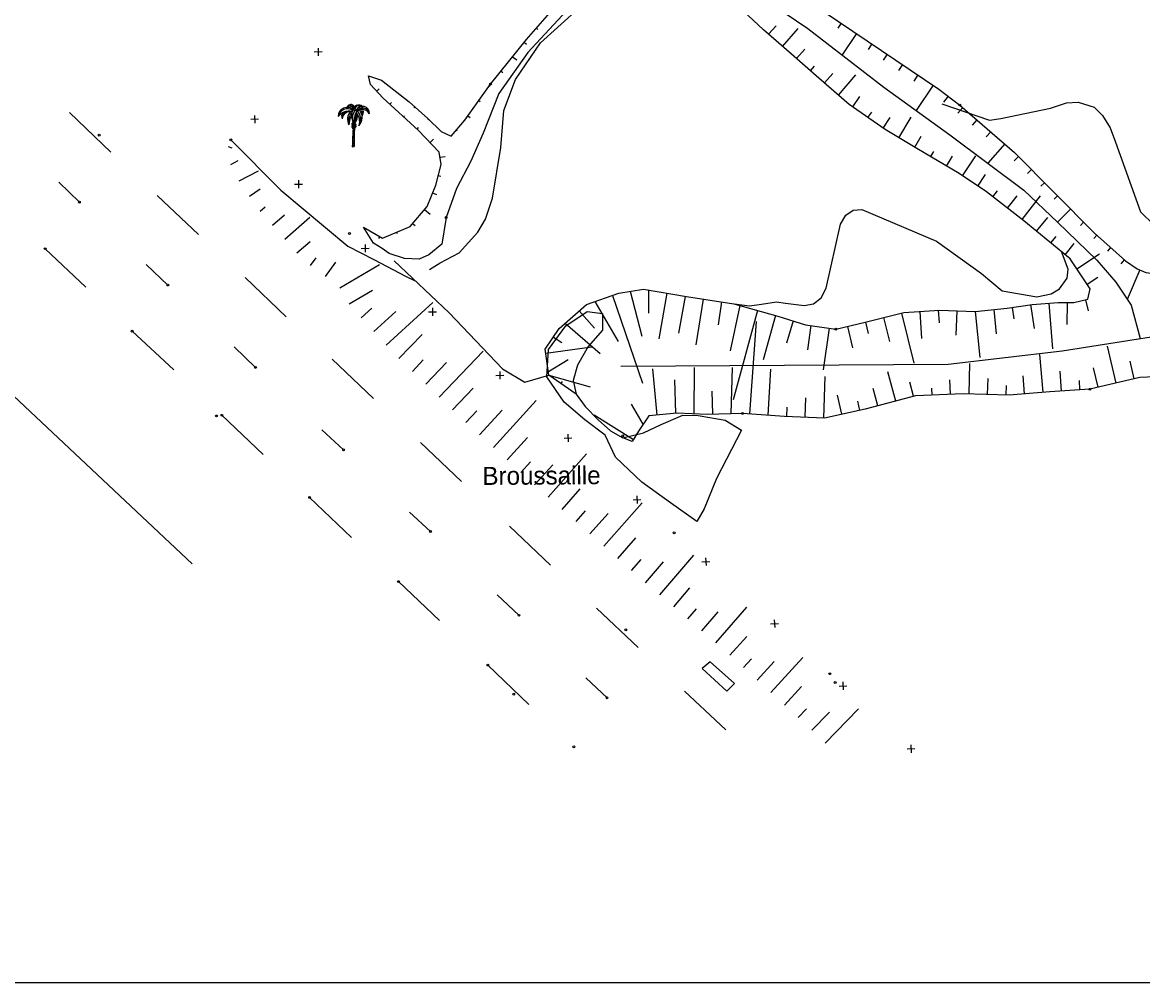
# Model space of a CAD drawing. Extents: x 344013 to 344423, y 298505 to 298795.
# Drawn here: x 344122.6 to 344183.1, y 298504.9 to 298556.7 of the extents above; entities that cross this region are included whole.
import ezdxf

# ---------------------------------------------------------------- set-up
doc = ezdxf.new("R2010")
doc.units = 0
for name, color, linetype in [('Default', 7, 'Continuous'), ('DH_CADRE -CARTOUCHE', 7, 'Continuous'), ('IMM_DIVERS', 7, 'Continuous'), ('IMM_VOIRIE VOIE FERREE', 7, 'Continuous'), ('PC_CONCRETE', 7, 'Continuous'), ('PS_CONST', 7, 'Continuous'), ('PS_DAWA', 7, 'Continuous'), ('PS_KOTE', 7, 'Continuous'), ('PS_WELD', 7, 'Continuous'), ('TOPO_COURBE NIVEAU', 7, 'Continuous'), ('TOPO_POINT', 7, 'Continuous'), ('TOPO_TALUS-TERRAIN NATUREL', 7, 'Continuous'), ('VOIRIE_ESPACE VERT', 7, 'Continuous')]:
    doc.layers.add(name, color=color, linetype=linetype)

# ---------------------------------------------------------------- blocks, each defined once
blk = doc.blocks.new('POINT_DISPLAY')
at = {"layer": 'Default'}
blk.add_circle((0, 0), 0.05, dxfattribs=at)
blk = doc.blocks.new('PALMIER')
at = {"layer": 'Default'}
for p, q in [((-0.036, 0.77), (0.064, 0.807)), ((0.066, 0.879), (-0.031, 0.865)), ((-0.027, 0.942), (0.068, 0.953)), ((0.07, 1.023), (-0.02, 1.046)), ((-0.016, 1.111), (0.072, 1.097)), ((-0.062, 0.035), (0.058, 0.076)), ((0.058, 0.159), (-0.059, 0.156)), ((-0.057, 0.24), (0.058, 0.243)), ((0.058, 0.341), (-0.054, 0.323)), ((-0.051, 0.409), (0.059, 0.425)), ((0.06, 0.53), (-0.047, 0.516))]:
    blk.add_line(p, q, dxfattribs=at)
blk.add_lwpolyline([(-0.044, 0.591), (0.061, 0.593), (0.062, 0.664), (-0.041, 0.672)], dxfattribs=at)
for centre, radius, start, end in [((-0.427, 2.014), 0.606, 43.75383, 181.60417), ((-0.287, 1.433), 0.935, 76.88066, 142.94423), ((-0.379, 1.861), 0.66, 58.06089, 166.76184), ((-0.191, 1.77), 0.575, 78.65572, 171.49215), ((-0.318, 1.955), 0.441, 119.22507, 188.90379), ((-0.119, 2.5), 0.329, 122.48917, 158.90528), ((-0.196, 2.528), 0.242, 4.66355, 154.2427), ((-0.249, 2.465), 0.236, 4.38583, 134.35204), ((0.377, 1.821), 0.768, 136.85301, 208.9638), ((0.57, 1.687), 0.895, 137.87473, 194.5133), ((-0.156, 2.558), 0.26, 21.2278, 122.48917), ((0.64, 2.063), 0.767, 153.22849, 230.25415), ((0.679, 1.97), 0.731, 142.49709, 222.42113), ((0, 2.373), 0.0573, 81.88924, 144.44525), ((-0.182, 1.095), 1.349, 71.51318, 81.88924), ((0.39, 2.418), 0.379, 113.90981, 175.47265), ((0.39, 2.418), 0.379, 113.90981, 175.47265), ((0.306, 2.506), 0.261, 198.81826, 199.90438), ((0.989, 1.84), 0.917, 144.12827, 203.57056), ((0.433, 2.437), 0.332, 97.26656, 184.09287), ((1.052, 1.956), 0.976, 126.82753, 153.3081), ((0.609, 1.916), 0.559, 29.70715, 139.49343), ((-0.544, 1.637), 0.978, 345.01981, 41.28777), ((-0.338, 1.796), 0.844, 47.11841, 50.26484), ((0.636, 2.223), 0.459, 356.30437, 159.14261), ((0.629, 2.092), 0.477, 12.24944, 148.4563), ((0.357, 2.315), 0.459, 69.22345, 105.00376), ((-0.152, 1.926), 0.754, 51.38923, 54.66342), ((-0.338, 1.796), 0.844, 334.21038, 41.33572), ((-1.014, 1.466), 1.819, 37.7085, 40.65735), ((-0.152, 1.926), 0.754, 315.28888, 39.16564), ((-0.251, 2.185), 0.885, 28.61423, 37.23825), ((0.508, 2.682), 0.0691, 35.46223, 126.82753), ((-1.727, 1.741), 2.37, 7.73955, 16.5083), ((-0.048, 2.285), 0.752, 25.96116, 35.46223), ((-0.251, 2.185), 0.885, 351.03001, 14.84805), ((-0.484, 2.461), 1.182, 339.50138, 356.73425), ((-0.298, 2.021), 0.491, 151.27485, 199.73594), ((0.671, 1.493), 0.966, 145.65628, 182.59451), ((-0.285, 1.344), 0.284, 348.96741, 47.50384), ((24.236, -0.46), 24.303, 175.11756, 178.94339), ((-0.275, 1.529), 0.286, 2.29159, 36.77418), ((-0.586, 1.323), 0.604, 357.22259, 24.49773), ((-0.26, 1.395), 0.322, 340.14145, 25.86455), ((0.212, 1.553), 0.18, 167.08602, 185.73834), ((27.948, 0.208), 27.89, 177.28613, 180.41366), ((0.563, 1.714), 0.483, 137.33705, 173.04039), ((0.322, 1.915), 0.23, 121.57139, 182.43168), ((27.823, 0.039), 27.774, 175.62083, 176.70143), ((0.325, 2.055), 0.223, 141.99767, 191.65918), ((0.388, 1.745), 0.282, 133.73732, 173.62872), ((0.832, 1.435), 0.791, 142.37749, 156.42174), ((0.255, 1.864), 0.149, 111.11446, 166.11729), ((0.42, 1.776), 0.361, 125.20026, 146.53098), ((0.414, 2.001), 0.306, 136.59859, 162.21026), ((0.372, 1.986), 0.249, 133.26007, 172.89513), ((-0.764, 1.855), 0.939, 344.99226, 16.04048), ((-0.403, 1.944), 0.63, 329.60827, 26.82103), ((-0.287, 2.01), 0.575, 317.96962, 12.48027), ((-0.205, 1.197), 0.169, 353.50598, 55.12107), ((-0.721, 1.091), 0.712, 9.15549, 26.66867), ((-0.349, 1.239), 0.371, 353.62318, 41.34943), ((0.287, 1.204), 0.266, 120.40763, 191.54922), ((0.343, 1.162), 0.295, 120.97799, 179.22943), ((0.244, 1.306), 0.167, 110.73571, 185.35669), ((0.507, 1.019), 0.45, 131.01759, 160.16859)]:
    blk.add_arc(centre, radius, start, end, dxfattribs=at)

msp = doc.modelspace()

# ---------------------------------------------------------------- linework, layer by layer
at = {"layer": 'DH_CADRE -CARTOUCHE'}
msp.add_lwpolyline([(344012.906, 298504.876), (344422.906, 298504.876), (344422.906, 298791.876), (344012.906, 298791.876)], close=True, dxfattribs=at)
at = {"layer": 'IMM_DIVERS'}
for centre in [(344151.975, 298528.79), (344140.897, 298525.565)]:
    msp.add_arc(centre, 1, 0, 0, dxfattribs=at)
at = {"layer": 'IMM_VOIRIE VOIE FERREE'}
for points in [[(344127.346, 298549.738), (344125.107, 298551.875)], [(344125.639, 298547.029), (344124.523, 298548.117)], [(344132.077, 298545.276), (344129.837, 298547.397)], [(344123.791, 298544.517), (344125.99, 298542.437)], [(344130.414, 298542.553), (344129.244, 298543.664)], [(344136.806, 298540.831), (344134.598, 298542.952)], [(344128.495, 298540.066), (344130.735, 298537.978)], [(344135.16, 298538.107), (344133.997, 298539.21)], [(344141.52, 298536.432), (344139.289, 298538.545)], [(344133.343, 298535.519), (344135.566, 298533.399)], [(344139.914, 298533.653), (344138.735, 298534.741)], [(344146.274, 298531.947), (344144.059, 298534.043)], [(344138.078, 298531.083), (344140.341, 298528.924)], [(344144.612, 298529.238), (344143.481, 298530.279)], [(344151.096, 298527.424), (344148.882, 298529.52)], [(344142.879, 298526.535), (344145.095, 298524.438)], [(344149.388, 298524.714), (344148.21, 298525.818)], [(344155.833, 298522.971), (344153.578, 298525.107)], [(344147.702, 298522.027), (344149.917, 298519.898)], [(344154.142, 298520.26), (344153.002, 298521.342)], [(344160.554, 298518.534), (344158.323, 298520.614)]]:
    msp.add_lwpolyline(points, dxfattribs=at)
at = {"layer": 'PC_CONCRETE'}
msp.add_lwpolyline([(344142.636, 298543.855), (344145.621, 298541.05), (344148.504, 298538.031), (344149.7, 298537.305), (344151.002, 298537.69), (344153.228, 298537.051)], dxfattribs=at)
at = {"layer": 'PS_DAWA'}
msp.add_lwpolyline([(344017.676, 298634.726), (344131.741, 298527.493)], dxfattribs=at)
at = {"layer": 'PS_KOTE'}
msp.add_lwpolyline([(344159.287, 298521.843), (344160.623, 298520.612), (344161.025, 298521.029), (344159.721, 298522.195), (344159.287, 298521.843)], dxfattribs=at)
at = {"layer": 'PS_WELD'}
for p, q in [((344138.754, 298555.144), (344138.33, 298555.132)), ((344138.536, 298555.35), (344138.548, 298554.926)), ((344135.318, 298551.511), (344134.894, 298551.499)), ((344135.1, 298551.717), (344135.112, 298551.293)), ((344137.474, 298548.214), (344137.481, 298547.79)), ((344137.265, 298547.998), (344137.69, 298548.005)), ((344140.869, 298544.53), (344141.293, 298544.542)), ((344141.075, 298544.748), (344141.087, 298544.324)), ((344144.506, 298541.098), (344144.93, 298541.111)), ((344144.712, 298541.317), (344144.724, 298540.893)), ((344148.349, 298537.885), (344148.361, 298537.461)), ((344148.143, 298537.667), (344148.567, 298537.679)), ((344151.823, 298534.277), (344152.247, 298534.301)), ((344152.023, 298534.501), (344152.047, 298534.077)), ((344155.55, 298530.945), (344155.974, 298530.968)), ((344155.75, 298531.168), (344155.774, 298530.745)), ((344159.269, 298527.604), (344159.693, 298527.625)), ((344159.47, 298527.826), (344159.492, 298527.402)), ((344162.978, 298524.25), (344163.402, 298524.272)), ((344163.179, 298524.473), (344163.201, 298524.049)), ((344166.68, 298520.892), (344167.104, 298520.908)), ((344166.883, 298521.112), (344166.9, 298520.688)), ((344170.351, 298517.498), (344170.775, 298517.514)), ((344170.555, 298517.718), (344170.572, 298517.294))]:
    msp.add_line(p, q, dxfattribs=at)
at = {"layer": 'TOPO_COURBE NIVEAU'}
for points in [[(344144.559, 298543.398), (344145.126, 298543.758), (344146.164, 298544.291), (344147.173, 298545.407), (344147.575, 298546.106), (344147.955, 298547.238), (344148.408, 298549.983), (344148.576, 298551.974), (344149.201, 298553.647), (344150.556, 298555.627), (344153.701, 298558.494), (344155.669, 298559.733), (344159.453, 298560.805), (344165.265, 298563.828)], [(344172.229, 298552.34), (344174.81, 298551.459), (344175.417, 298551.545), (344178.101, 298552.1), (344178.967, 298552.397), (344179.598, 298552.428), (344180.464, 298552.159), (344180.902, 298551.719), (344181.319, 298551.048), (344181.616, 298550.278), (344182.963, 298546.5), (344184.44, 298545.064), (344185.14, 298544.773), (344186.698, 298544.755), (344187.508, 298545.028), (344188.162, 298545.491), (344188.533, 298546.018), (344189.189, 298547.821), (344189.573, 298551.818), (344189.112, 298553.182), (344189.034, 298554.487), (344189.312, 298556.099), (344189.48, 298557.412)], [(344161.011, 298541.531), (344161.835, 298541.435), (344162.489, 298541.521), (344163.292, 298541.645), (344163.787, 298541.574), (344164.801, 298541.439), (344165.305, 298541.532), (344165.715, 298541.862), (344165.983, 298542.381), (344166.752, 298545.848), (344167.036, 298546.319), (344167.438, 298546.595), (344167.902, 298546.633), (344171.944, 298544.926), (344174.372, 298543.184), (344175.479, 298542.247), (344177.36, 298541.921), (344178.139, 298542.085), (344178.58, 298542.352), (344179.006, 298542.933), (344179.054, 298543.405), (344178.687, 298544.359)]]:
    msp.add_lwpolyline(points, dxfattribs=at)
at = {"layer": 'TOPO_TALUS-TERRAIN NATUREL'}
for p, q in [((344166.793, 298556.702), (344166.605, 298556.424)), ((344150.325, 298556.424), (344150.398, 298556.361)), ((344162.871, 298556.096), (344163.272, 298556.558)), ((344163.626, 298555.44), (344164.472, 298556.414)), ((344167.621, 298556.142), (344166.836, 298554.98)), ((344149.674, 298555.665), (344149.802, 298555.562)), ((344168.45, 298555.582), (344168.244, 298555.278)), ((344149.045, 298554.887), (344149.265, 298554.71)), ((344164.38, 298554.783), (344164.828, 298555.295)), ((344169.278, 298555.022), (344169.064, 298554.705)), ((344165.133, 298554.125), (344165.346, 298554.368)), ((344170.107, 298554.462), (344169.884, 298554.133)), ((344141.287, 298553.836), (344141.279, 298553.812)), ((344148.417, 298554.109), (344148.511, 298554.033)), ((344165.887, 298553.467), (344166.334, 298553.982)), ((344166.642, 298552.812), (344167.586, 298553.898)), ((344170.935, 298553.902), (344170.708, 298553.566)), ((344141.705, 298553.025), (344141.842, 298553.153)), ((344142.19, 298553.436), (344142.181, 298553.424)), ((344147.794, 298553.327), (344147.835, 298553.297)), ((344171.764, 298553.342), (344170.839, 298551.974)), ((344142.415, 298552.322), (344142.497, 298552.412)), ((344142.982, 298552.824), (344142.961, 298552.797)), ((344147.213, 298552.512), (344147.285, 298552.461)), ((344167.413, 298552.175), (344167.803, 298552.736)), ((344172.572, 298552.754), (344172.324, 298552.426)), ((344143.753, 298552.188), (344143.699, 298552.129)), ((344168.234, 298551.604), (344168.44, 298551.899)), ((344173.361, 298552.14), (344173.096, 298551.835)), ((344143.154, 298551.648), (344143.197, 298551.695)), ((344144.492, 298551.514), (344144.459, 298551.481)), ((344146.633, 298551.697), (344146.756, 298551.61)), ((344169.055, 298551.032), (344169.446, 298551.594)), ((344169.908, 298550.511), (344170.575, 298551.627)), ((344174.115, 298551.483), (344173.863, 298551.194)), ((344143.892, 298550.973), (344143.966, 298551.054)), ((344145.213, 298550.824), (344145.202, 298550.799)), ((344146.008, 298550.917), (344146.057, 298550.876)), ((344170.767, 298549.998), (344171.119, 298550.587)), ((344174.87, 298550.827), (344174.63, 298550.552)), ((344133.686, 298550.042), (344133.885, 298549.964)), ((344144.584, 298550.251), (344144.772, 298550.428)), ((344175.624, 298550.171), (344174.716, 298549.127)), ((344145.122, 298549.451), (344145.404, 298549.494)), ((344171.626, 298549.487), (344171.793, 298549.767)), ((344172.486, 298548.975), (344172.802, 298549.507)), ((344173.339, 298548.454), (344174.068, 298549.537)), ((344176.364, 298549.498), (344176.133, 298549.27)), ((344133.816, 298549.071), (344134.218, 298549.276)), ((344177.068, 298548.788), (344176.864, 298548.586)), ((344134.271, 298548.18), (344135.318, 298548.716)), ((344145.028, 298548.475), (344145.159, 298548.441)), ((344174.169, 298547.895), (344174.596, 298548.53)), ((344134.835, 298547.354), (344135.402, 298547.747)), ((344144.722, 298547.525), (344144.936, 298547.438)), ((344174.983, 298547.315), (344175.229, 298547.634)), ((344177.772, 298548.078), (344177.584, 298547.892)), ((344175.776, 298546.704), (344176.296, 298547.38)), ((344176.568, 298546.094), (344177.556, 298547.377)), ((344178.476, 298547.368), (344178.294, 298547.187)), ((344135.411, 298546.537), (344135.685, 298546.778)), ((344136.072, 298545.786), (344136.712, 298546.349)), ((344144.289, 298546.633), (344144.59, 298546.378)), ((344179.18, 298546.658), (344178.471, 298545.955)), ((344136.732, 298545.035), (344138.084, 298546.224)), ((344143.643, 298545.868), (344143.772, 298545.76)), ((344177.343, 298545.462), (344177.946, 298546.194)), ((344179.885, 298545.948), (344179.711, 298545.776)), ((344141.865, 298545.177), (344141.803, 298545.07)), ((344142.778, 298545.404), (344142.806, 298545.338)), ((344178.115, 298544.826), (344178.4, 298545.175)), ((344180.595, 298545.245), (344180.435, 298545.066)), ((344137.393, 298544.284), (344138.106, 298544.911)), ((344178.89, 298544.193), (344179.377, 298544.79)), ((344181.341, 298544.579), (344181.173, 298544.391)), ((344138.127, 298543.614), (344138.424, 298544.017)), ((344179.522, 298543.431), (344180.74, 298544.242)), ((344182.086, 298543.912), (344181.896, 298543.7)), ((344138.933, 298543.021), (344139.497, 298543.787)), ((344139.712, 298542.403), (344141.846, 298543.666)), ((344182.921, 298543.368), (344182.249, 298541.774)), ((344180.076, 298542.598), (344180.655, 298542.984)), ((344140.221, 298541.542), (344141.472, 298542.282)), ((344155.402, 298542.214), (344156.027, 298539.793)), ((344156.387, 298542.29), (344156.386, 298541.04)), ((344157.372, 298542.115), (344156.935, 298539.653)), ((344142.213, 298539.303), (344144.739, 298541.602)), ((344153.485, 298541.659), (344154.742, 298539.496)), ((344154.431, 298541.984), (344156.057, 298537.254)), ((344158.357, 298541.94), (344158.005, 298539.96)), ((344159.345, 298541.788), (344158.938, 298539.32)), ((344160.334, 298541.637), (344160.145, 298540.401)), ((344177.011, 298541.496), (344177.212, 298540.199)), ((344178.007, 298541.58), (344178.198, 298539.1)), ((344179.006, 298541.609), (344178.983, 298540.43)), ((344179.987, 298541.758), (344180.136, 298541.156)), ((344140.866, 298540.782), (344141.433, 298541.298)), ((344141.54, 298540.042), (344142.736, 298541.132)), ((344152.641, 298541.159), (344153.466, 298540.221)), ((344161.315, 298541.448), (344160.793, 298539.002)), ((344162.279, 298541.182), (344160.95, 298536.361)), ((344163.243, 298540.916), (344162.579, 298538.506)), ((344170.042, 298541.038), (344170.721, 298538.335)), ((344171.036, 298541.131), (344171.135, 298539.667)), ((344172.034, 298541.198), (344172.081, 298540.504)), ((344173.034, 298541.168), (344172.983, 298539.851)), ((344174.033, 298541.131), (344174.279, 298538.645)), ((344175.029, 298541.229), (344175.158, 298539.92)), ((344176.022, 298541.342), (344176.118, 298540.726)), ((344151.89, 298540.499), (344153.772, 298538.853)), ((344161.852, 298535.592), (344162.224, 298540.579)), ((344164.197, 298540.616), (344163.84, 298539.418)), ((344165.161, 298540.36), (344164.971, 298539.045)), ((344167.13, 298540.315), (344167.411, 298539.155)), ((344168.102, 298540.551), (344168.255, 298539.941)), ((344169.072, 298540.795), (344169.394, 298539.511)), ((344142.905, 298538.581), (344144.152, 298539.882)), ((344151.248, 298539.742), (344151.697, 298539.443)), ((344166.151, 298540.217), (344165.827, 298537.973)), ((344150.837, 298538.877), (344153.314, 298539.222)), ((344181.65, 298537.26), (344181.179, 298539.252)), ((344143.627, 298537.889), (344144.219, 298538.507)), ((344145.072, 298536.505), (344147.445, 298538.981)), ((344150.975, 298537.887), (344152.043, 298538.537)), ((344177.694, 298536.762), (344177.528, 298538.794)), ((344182.624, 298537.49), (344182.4, 298538.436)), ((344144.35, 298537.197), (344145.474, 298538.37)), ((344156.859, 298535.531), (344156.619, 298538.021)), ((344158.854, 298535.598), (344158.87, 298538.098)), ((344160.853, 298535.605), (344160.912, 298538.105)), ((344162.85, 298535.518), (344162.99, 298538.014)), ((344169.738, 298536.289), (344169.314, 298537.871)), ((344173.7, 298536.672), (344173.744, 298538.316)), ((344178.692, 298536.829), (344178.627, 298537.903)), ((344180.677, 298537.029), (344180.429, 298538.078)), ((344151.657, 298537.227), (344151.736, 298537.339)), ((344157.854, 298535.627), (344157.804, 298537.435)), ((344165.846, 298535.371), (344165.932, 298537.607)), ((344170.704, 298536.548), (344170.503, 298537.299)), ((344172.7, 298536.652), (344172.668, 298537.431)), ((344174.699, 298536.645), (344174.723, 298537.512)), ((344176.697, 298536.68), (344176.618, 298537.643)), ((344179.69, 298536.889), (344179.66, 298537.399)), ((344145.794, 298535.813), (344146.921, 298536.989)), ((344159.853, 298535.578), (344159.819, 298536.827)), ((344168.772, 298536.031), (344168.524, 298536.956)), ((344171.701, 298536.611), (344171.685, 298536.98)), ((344175.699, 298536.618), (344175.713, 298537.126)), ((344148.002, 298533.782), (344150.324, 298536.325)), ((344156.097, 298535.041), (344155.459, 298536.117)), ((344164.847, 298535.41), (344164.887, 298536.469)), ((344166.825, 298535.573), (344166.6, 298536.611)), ((344167.802, 298535.785), (344167.696, 298536.278)), ((344146.525, 298535.13), (344147.104, 298535.765)), ((344147.263, 298534.456), (344148.486, 298535.795)), ((344155.566, 298534.194), (344153.451, 298535.528)), ((344163.847, 298535.448), (344163.866, 298535.95)), ((344148.741, 298533.107), (344149.843, 298534.315)), ((344149.48, 298532.433), (344150.003, 298533.006)), ((344150.967, 298531.095), (344153.026, 298533.43)), ((344150.219, 298531.759), (344151.213, 298532.848)), ((344151.718, 298530.434), (344152.695, 298531.543)), ((344153.969, 298528.45), (344156.036, 298530.794)), ((344152.468, 298529.772), (344152.984, 298530.357)), ((344153.219, 298529.111), (344154.198, 298530.222)), ((344154.719, 298527.788), (344155.7, 298528.901)), ((344155.471, 298527.128), (344155.98, 298527.722)), ((344156.23, 298526.477), (344157.198, 298527.606)), ((344156.99, 298525.826), (344158.828, 298527.971)), ((344157.749, 298525.175), (344158.622, 298526.194)), ((344160.028, 298523.223), (344161.689, 298525.161)), ((344158.509, 298524.524), (344158.969, 298525.062)), ((344159.268, 298523.873), (344160.143, 298524.894)), ((344160.783, 298522.567), (344161.691, 298523.562)), ((344161.522, 298521.893), (344161.953, 298522.365)), ((344162.261, 298521.218), (344163.171, 298522.215)), ((344162.999, 298520.544), (344164.728, 298522.437)), ((344163.738, 298519.869), (344164.65, 298520.868)), ((344164.477, 298519.195), (344164.91, 298519.669)), ((344165.21, 298518.514), (344166.154, 298519.486)), ((344165.927, 298517.817), (344167.721, 298519.663))]:
    msp.add_line(p, q, dxfattribs=at)
for points in [[(344140.996, 298545.673), (344142.019, 298545.089), (344143.508, 298545.707), (344144.43, 298546.8), (344144.896, 298547.955), (344145.181, 298549.072), (344145.08, 298549.726), (344143.964, 298550.907), (344142.041, 298552.664), (344141.365, 298553.39), (344141.256, 298553.846), (344141.956, 298553.617), (344143.457, 298552.457), (344144.457, 298551.549), (344145.179, 298550.84), (344145.73, 298550.587), (344146.464, 298551.459), (344147.852, 298553.408), (344149.8, 298555.822), (344152.196, 298558.572), (344154.419, 298561.118), (344155.902, 298562.612), (344156.573, 298563.169)], [(344156.573, 298563.169), (344155.057, 298560.622), (344151.713, 298557.116), (344149.869, 298555.121), (344148.299, 298552.896), (344147.446, 298550.756), (344146.782, 298549.246), (344146.008, 298547.768), (344145.446, 298546.202), (344145.223, 298544.768), (344144.523, 298544.18), (344143.995, 298543.952), (344143.209, 298543.985), (344142.383, 298544.262), (344141.99, 298544.53), (344141.526, 298544.807), (344140.996, 298545.673)], [(344159.089, 298561.039), (344159.354, 298561.091), (344159.742, 298561.084), (344160.297, 298560.96), (344160.706, 298560.777), (344161.231, 298560.46), (344172.069, 298553.135), (344173.202, 298552.277), (344176.155, 298549.708), (344180.474, 298545.354), (344182.152, 298543.854), (344182.779, 298543.428), (344183.25, 298543.23), (344183.942, 298543.143), (344184.794, 298543.131), (344197.63, 298543.79), (344202.568, 298544.192), (344226.369, 298544.819)], [(344158.923, 298560.537), (344164.997, 298556.401), (344169.095, 298553.232), (344172.662, 298550.66), (344176.659, 298547.676), (344178.472, 298545.954), (344180.609, 298543.896), (344181.623, 298542.715), (344182.451, 298541.471), (344182.948, 298539.664)], [(344152.474, 298536.65), (344151.002, 298537.69), (344150.808, 298539.082), (344151.557, 298540.207), (344153.03, 298541.502), (344154.786, 298542.106), (344156.109, 298542.339), (344158.437, 298541.926), (344160.993, 298541.536), (344163.377, 298540.879), (344164.858, 298540.404), (344166.51, 298540.165), (344168.092, 298540.549), (344170.181, 298541.073), (344172.111, 298541.203), (344174.024, 298541.13), (344175.756, 298541.301), (344177.103, 298541.51), (344178.504, 298541.618), (344179.356, 298541.602), (344180.111, 298541.789), (344180.238, 298542.356), (344179.162, 298543.971), (344178.062, 298544.869), (344176.665, 298546.02), (344174.639, 298547.579), (344173.161, 298548.573), (344170.88, 298549.931), (344169.174, 298550.949), (344167.225, 298552.306), (344165.591, 298553.724), (344164.113, 298555.017), (344162.596, 298556.335), (344160.685, 298558.13)], [(344133.823, 298550.393), (344136.523, 298547.683), (344140.147, 298544.646), (344141.539, 298543.927), (344143.294, 298543.019), (344143.783, 298542.778)], [(344154.898, 298538.173), (344172.574, 298538.285), (344178.724, 298539.008), (344184.798, 298539.951), (344190.475, 298540.627), (344196.057, 298540.894), (344200.363, 298541.02), (344205.66, 298540.877), (344210.998, 298541.058), (344214.704, 298540.981), (344226.887, 298542.078), (344234.332, 298542.806), (344240.181, 298542.741), (344244.62, 298541.963), (344249.438, 298542.301), (344254.988, 298542.441), (344260.239, 298542.252), (344263.443, 298542.475), (344268.331, 298542.177), (344273.659, 298541.766), (344276.981, 298541.619), (344282.364, 298541.26)], [(344185.371, 298537.668), (344182.931, 298537.563), (344180.219, 298536.921), (344178.054, 298536.791), (344175.872, 298536.613), (344173.384, 298536.68), (344170.799, 298536.574), (344168.083, 298535.846), (344165.887, 298535.37), (344163.729, 298535.452), (344161.454, 298535.622), (344159.557, 298535.569), (344157.936, 298535.635), (344156.4, 298535.487), (344155.839, 298534.661), (344155.508, 298534.096), (344154.997, 298534.309)]]:
    msp.add_lwpolyline(points, dxfattribs=at)
at = {"layer": 'VOIRIE_ESPACE VERT'}
msp.add_lwpolyline([(344161.409, 298534.711), (344160.06, 298532.109), (344159.396, 298530.457), (344158.994, 298529.773), (344157.563, 298530.798), (344156.015, 298531.911), (344154.6, 298533.25), (344154.036, 298534.447), (344152.944, 298535.275), (344151.828, 298536.221), (344150.9, 298537.594), (344150.989, 298539.067), (344151.921, 298540.357), (344153.064, 298541.118), (344153.906, 298541.015), (344153.897, 298540.11), (344153.124, 298539.23), (344152.54, 298538.224), (344152.31, 298537.399), (344152.474, 298536.65), (344152.962, 298535.988), (344153.668, 298535.264), (344154.336, 298534.672), (344154.997, 298534.309), (344156.107, 298534.567), (344157.075, 298535.013), (344158.233, 298535.524), (344159.075, 298535.514), (344160.532, 298535.253), (344161.409, 298534.711)], dxfattribs=at)

# ---------------------------------------------------------------- block references
at = {"layer": 'TOPO_POINT'}
for p in [(344147.852, 298553.408), (344173.202, 298552.277), (344126.717, 298550.647), (344133.823, 298550.393), (344140.438, 298550.051), (344125.639, 298547.029), (344145.446, 298546.202), (344140.235, 298545.334), (344123.791, 298544.517), (344130.414, 298542.553), (344128.495, 298540.066), (344166.51, 298540.165), (344135.16, 298538.107), (344180.219, 298536.921), (344133.045, 298535.481), (344133.343, 298535.519), (344161.454, 298535.622), (344154.992, 298534.412), (344139.914, 298533.653), (344138.078, 298531.083), (344144.612, 298529.238), (344157.765, 298529.166), (344142.879, 298526.535), (344149.388, 298524.714), (344155.153, 298523.931), (344147.702, 298522.027), (344166.179, 298521.559), (344166.467, 298521.08), (344149.102, 298520.459), (344154.142, 298520.26), (344152.354, 298517.612)]:
    msp.add_blockref('POINT_DISPLAY', p, dxfattribs=at)
at = {"layer": 'VOIRIE_ESPACE VERT', "xscale": 0.8, "yscale": 0.8000000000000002}
msp.add_blockref('PALMIER', (344140.438, 298550.051), dxfattribs=at)

# ---------------------------------------------------------------- texts
at = {"layer": 'PS_CONST'}
msp.add_text('Broussaille', height=0.97578, rotation=0.36655, dxfattribs=at).set_placement((344147.416, 298531.755))

doc.saveas('drawing.dxf')
